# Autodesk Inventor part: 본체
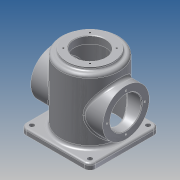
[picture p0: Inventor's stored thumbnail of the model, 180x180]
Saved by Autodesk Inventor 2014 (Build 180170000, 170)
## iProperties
Created: 2015-10
Part Number: 본체
Material: 알루미늄 6061
Document SubType Name: Modeling
Designer: 시험용
Density: 2.71 g/cm^3
Appearance: 알루미늄 - 평지
Mass: 985.998 g
Surface Area: 1037.33 cm^2
Volume: 363.837 cm^3
Author: 시험용
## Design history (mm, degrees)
sketch "스케치1"
  geometry: L1 (0, 0)-(-125, 0); L2 (-125, 27)-(-125, 40); L3 (-125, 40)-(-120, 40); L4 (-120, 40)-(-120, 50); L5 (-120, 50)-(0, 50); L6 (0, 50)-(0, 45); L7 (0, 45)-(-112, 45); L8 (-112, 45)-(-112, 27); L9 (-112, 27)-(-125, 27)
  constraints: 18 end point, 6 parallel, 2 perpendicular, 2 vertical alignment, 1 horizontal
  dimensions: "d0" = 125 distance between parallel lines of L2 L6; "d2" = 120 distance between parallel lines of L6 L4; "d3" = 112 distance from line of L6.end L8; "d4" = 54 diameter of L9 L1; "d5" = 90 diameter of L7 L1; "d6" = 100 diameter of L5 L1; "d7" = 80 diameter of L3 L1
revolve "회전1" sketch "스케치1" stored, may be unused: angle "d8" = 90 deg
sketch "스케치3"
  geometry: C1 r 40 at (-60, 0); C2 r 27 at (-60, 0); 1 further point
  constraints: 2 centre point, 1 horizontal alignment
  dimensions: "d25" = 80 diameter of C1; "d26" = 60 distance of point (0, 0) C1.centre; "d27" = 54 diameter of C2
extrude "돌출1" join sketch "스케치3" stored distance "d28" = 124; taper "d29" = 0 deg
hole "구멍2" diameter "d32" = 54; stored, may be unused: countersink angle "d36" = 90 deg, drill point angle "d38" = 118 deg; dims "d30" = 10, "d31" = 10, "d33" = 6, "d34" = 4, "d35" = 2, "d37" = 8
hole "구멍3" diameter "d41" = 90; stored, may be unused: countersink angle "d45" = 90 deg, drill point angle "d47" = 0 deg; dims "d42" = 6, "d43" = 4, "d44" = 2, "d46" = 110, "d50" = 10, "d51" = 10
chamfer "모따기1" distance "d48" = 1; stored, may be unused: second distance "d49" = 2, angle "d52" = 45 deg
sketch "스케치4"
  geometry: L1 (-50, -60)-(50, -60); L2 (60, -50)-(60, 50); L3 (50, 60)-(-50, 60); L4 (-60, 50)-(-60, -50); L5 (-60, -60)-(60, 60); L6 (60, -60)-(-60, 60); C1 r 50 at (0, 0) reference; C2 r 4 at (-50, 50); C3 r 4 at (50, 50); C4 r 4 at (50, -50); C5 r 4 at (-50, -50); C6 r 50 at (0, 0); A1 r 10 centre (-50, 50) between (-50, 60) and (-60, 50); A2 r 10 centre (-50, -50) between (-60, -50) and (-50, -60); A3 r 10 centre (50, -50) between (50, -60) and (60, -50); A4 r 10 centre (50, 50) between (60, 50) and (50, 60)
  constraints: 12 end point, 9 centre point, 8 point on circle, 8 point on line, 8 tangent, 7 equal radius, 5 coincident, 2 midpoint, 2 parallel, 1 horizontal, 1 perpendicular
  dimensions: "d54" = 120 distance of L5.end L6.end; "d55" = 120 distance of L6.end L5.start; "d56" = 10 radius of A1; "d57" = 8 diameter of C2
extrude "돌출2" join sketch "스케치4" distance "d58" = 10; taper "d59" = 0 deg
fillet "모깎기3" dims "d60" = 5
fillet "모깎기4" dims "d61" = 3
fillet "모깎기5" dims "d62" = 3
chamfer "모따기2" distance "d63" = 3; stored, may be unused: second distance "d64" = 2, angle "d65" = 45 deg
sketch "스케치5" dims "d67" = 65
  geometry: L1 (0, 40)-(0, 0); L2 (0, 0)-(28.284, 28.284); C1 r 28 at (0, 0) reference; A1 r 40 centre (0, 0) between (0, 40) and (28.284, 28.284) reference; 1 further point
  constraints: 4 end point, 2 point on circle, 1 point on line, 1 vertical, 3 other
  dimensions: "d66" = 45 deg angle of L1 L2
hole "구멍4" sketch "스케치5" at (22.981, 22.981) diameter "d68" = 3.242; stored, may be unused: countersink angle "d72" = 90 deg, drill point angle "d74" = 118 deg; dims "d69" = 8, "d70" = 4, "d71" = 2, "d73" = 10
sketch "스케치6" dims "d78" = 65
  geometry: C1 r 40 at (0, 0) reference; 2 further points
  constraints: 2 vertical alignment, 2 other
hole "구멍5" sketch "스케치6" at (0, 32.5) diameter "d79" = 3.242; stored, may be unused: countersink angle "d83" = 90 deg, drill point angle "d85" = 118 deg; dims "d80" = 8, "d81" = 4, "d82" = 2, "d84" = 10
sketch "스케치7" dims "d0" = 125, "d2" = 120, "d3" = 112, "d4" = 54, "d5" = 90, "d6" = 100, "d7" = 80, "d54" = 120, "d55" = 120, "d56" = 10, "d57" = 8
  geometry: L1 (0, 0)-(0, 100) reference; L2 (46.136, 53.377)-(93.864, 53.377); L3 (93.864, 53.377)-(93.864, 46.623); L4 (93.864, 46.623)-(46.136, 46.623); L5 (46.136, 46.623)-(46.136, 53.377); L6 (46.136, 53.377)-(93.864, 46.623); 4 further points
  constraints: 3 midpoint, 2 end point, 1 horizontal alignment, 1 vertical alignment, 2 other
  dimensions: "d89" = 70 distance of point (0, 50) point (70, 50); "d90" = 47.72772 distance of L2.start L2.end; "d91" = 6.75365 distance of L2.end L3.end
feature "엠보싱1" sketch "스케치7" dims "d0" = 125, "d2" = 120, "d3" = 112, "d4" = 54, "d5" = 90, "d6" = 100, "d7" = 80, "d42" = 6, "d92" = 0.5, "d93" = 0
fillet "모깎기6" dims "d94" = 3
fillet "모깎기7" dims "d95" = 3
node "솔리드1"
pattern_circular "원형 패턴1" dims angle "d76" = 360 deg
mirror "대칭1"
pattern_circular "원형 패턴2" dims angle "d87" = 360 deg
